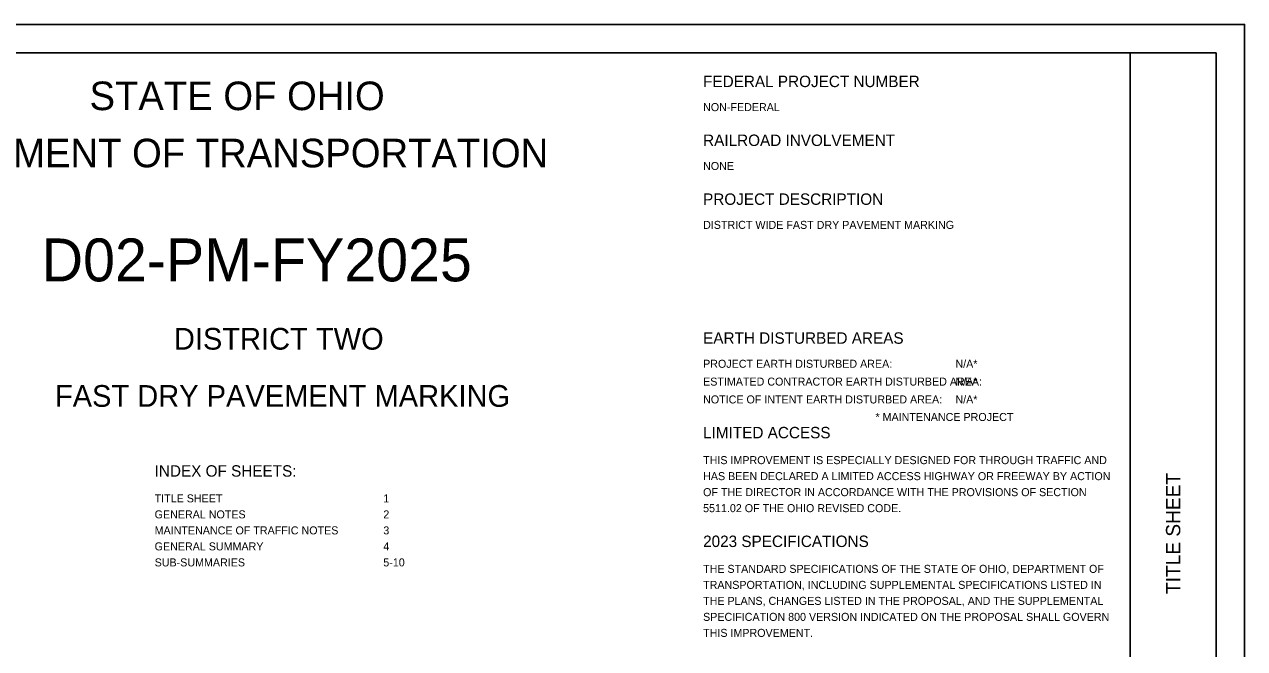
# Model space of a CAD drawing. Extents: x 0 to 34, y 0 to 22.
# Drawn here: x 12.66 to 34, y 11.08 to 22 of the extents above; entities that cross this region are included whole.
import ezdxf

# ---------------------------------------------------------------- set-up
doc = ezdxf.new("R2010")
doc.units = 0
for name, color, linetype in [('Default', 7, 'Continuous'), ('SH_Border', 7, 'Continuous'), ('SH_Cut_Line', 7, 'Continuous'), ('SH_Data', 7, 'Continuous'), ('SH_Text', 7, 'Continuous')]:
    doc.layers.add(name, color=color, linetype=linetype)

msp = doc.modelspace()

# ---------------------------------------------------------------- linework, layer by layer
at = {"layer": 'SH_Border'}
msp.add_line((32, 0.5), (32, 21.5), dxfattribs=at)
msp.add_lwpolyline([(1.5, 21.5), (33.5, 21.5), (33.5, 0.5), (1.5, 0.5)], close=True, dxfattribs=at)
at = {"layer": 'SH_Cut_Line'}
msp.add_lwpolyline([(0, 0), (34, 0), (34, 22), (0, 22)], close=True, dxfattribs=at)

# ---------------------------------------------------------------- texts
at = {"layer": 'Default'}
msp.add_text('* MAINTENANCE PROJECT', height=0.14, dxfattribs=at).set_placement((27.543, 15.062))
at = {"layer": 'SH_Data'}
msp.add_text('TITLE SHEET', height=0.25, rotation=90, dxfattribs=at).set_placement((32.875, 12.035))
at = {"layer": 'SH_Text'}
for s, height, p in [('STATE OF OHIO', 0.5, (13.795, 20.5)), ('FEDERAL PROJECT NUMBER', 0.2, (24.528, 20.903)), ('NON-FEDERAL ', 0.14, (24.528, 20.483)), ('RAILROAD INVOLVEMENT', 0.2, (24.528, 19.873)), ('DEPARTMENT OF TRANSPORTATION', 0.5, (9.747, 19.5)), ('NONE                ', 0.14, (24.528, 19.453)), ('PROJECT DESCRIPTION', 0.2, (24.528, 18.843)), ('DISTRICT WIDE FAST DRY PAVEMENT MARKING                ', 0.14, (24.528, 18.423)), ('D02-PM-FY2025', 0.75, (12.958, 17.505)), ('    DISTRICT TWO    ', 0.38, (14.706, 16.31)), ('EARTH DISTURBED AREAS', 0.2, (24.528, 16.413)), ('PROJECT EARTH DISTURBED AREA:', 0.14, (24.528, 15.993)), ('N/A*', 0.14, (28.942, 15.993)), ('ESTIMATED CONTRACTOR EARTH DISTURBED AREA:', 0.14, (24.528, 15.681)), ('N/A*', 0.14, (28.942, 15.681)), ('FAST DRY PAVEMENT MARKING', 0.38, (13.19, 15.31)), ('NOTICE OF INTENT EARTH DISTURBED AREA:', 0.14, (24.528, 15.369)), ('N/A*', 0.14, (28.942, 15.369)), ('LIMITED ACCESS', 0.2, (24.528, 14.759)), ('THIS IMPROVEMENT IS ESPECIALLY DESIGNED FOR THROUGH TRAFFIC AND', 0.14, (24.528, 14.307)), ('INDEX OF SHEETS:', 0.2, (14.934, 14.088)), ('HAS BEEN DECLARED A LIMITED ACCESS HIGHWAY OR FREEWAY BY ACTION', 0.14, (24.528, 14.027)), ('OF THE DIRECTOR IN ACCORDANCE WITH THE PROVISIONS OF SECTION', 0.14, (24.528, 13.747)), ('TITLE SHEET                        ', 0.14, (14.934, 13.638)), ('1      ', 0.14, (18.934, 13.638)), ('GENERAL NOTES                      ', 0.14, (14.934, 13.358)), ('2      ', 0.14, (18.934, 13.358)), ('5511.02 OF THE OHIO REVISED CODE.', 0.14, (24.528, 13.467)), ('MAINTENANCE OF TRAFFIC NOTES       ', 0.14, (14.934, 13.078)), ('3      ', 0.14, (18.934, 13.078)), ('2023 SPECIFICATIONS', 0.2, (24.528, 12.857)), ('GENERAL SUMMARY                    ', 0.14, (14.934, 12.798)), ('4      ', 0.14, (18.934, 12.798)), ('SUB-SUMMARIES                      ', 0.14, (14.934, 12.518)), ('5-10   ', 0.14, (18.934, 12.518)), ('THE STANDARD SPECIFICATIONS OF THE STATE OF OHIO, DEPARTMENT OF', 0.14, (24.528, 12.405)), ('TRANSPORTATION, INCLUDING SUPPLEMENTAL SPECIFICATIONS LISTED IN', 0.14, (24.528, 12.125)), ('THE PLANS, CHANGES LISTED IN THE PROPOSAL, AND THE SUPPLEMENTAL', 0.14, (24.528, 11.845)), ('SPECIFICATION 800 VERSION INDICATED ON THE PROPOSAL SHALL GOVERN', 0.14, (24.528, 11.565)), ('THIS IMPROVEMENT.', 0.14, (24.528, 11.285))]:
    msp.add_text(s, height=height, dxfattribs=at).set_placement(p)

doc.saveas('drawing.dxf')
